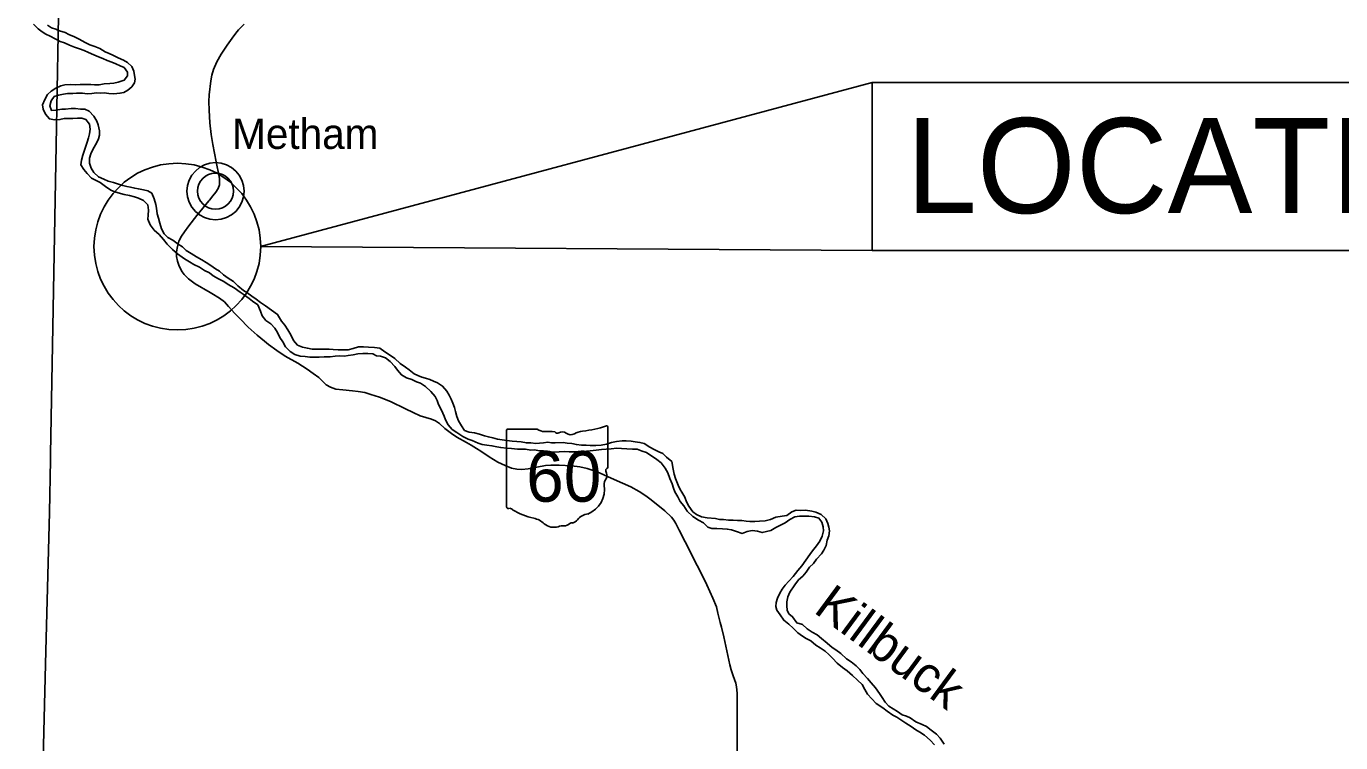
# Model space of a CAD drawing. Extents: x -6.3 to 34, y 0 to 22.
# Drawn here: x 1.879 to 4.228, y 15.677 to 16.958 of the extents above; entities that cross this region are included whole.
import ezdxf

# ---------------------------------------------------------------- set-up
doc = ezdxf.new("R2010")
doc.units = 0
for name, color, linetype in [('BR_P_Gen_Text', 7, 'Continuous'), ('Default', 7, 'Continuous'), ('GM_X_Major_River', 7, 'Continuous'), ('GM_X_Major_River_Text', 7, 'Continuous'), ('GM_X_State_Location', 7, 'Continuous'), ('GM_X_State_Route', 7, 'Continuous'), ('GM_X_State_Shield', 7, 'Continuous'), ('GM_X_Township', 7, 'Continuous'), ('GM_X_Unincorporated', 7, 'Continuous'), ('GM_X_Unincorporated_Location', 7, 'Continuous'), ('GM_X_Unincorporated_Text', 7, 'Continuous')]:
    doc.layers.add(name, color=color, linetype=linetype)

msp = doc.modelspace()

# ---------------------------------------------------------------- linework, layer by layer
at = {"layer": 'BR_P_Gen_Text'}
for points in [[(3.3908, 16.857), (3.3908, 16.5568), (2.2979, 16.5637)], [(3.3908, 16.857), (4.7995, 16.857), (4.7995, 16.5568), (3.3908, 16.5568)]]:
    msp.add_lwpolyline(points, close=True, dxfattribs=at)
at = {"layer": 'Default'}
msp.add_circle((2.149, 16.5637), 0.149, dxfattribs=at)
at = {"layer": 'GM_X_Major_River'}
for points in [[(1.8916, 16.9615), (1.9004, 16.9532), (1.9074, 16.9475), (1.9141, 16.9436), (1.9219, 16.94), (1.9307, 16.9353), (1.9398, 16.9307), (1.9471, 16.9278), (1.9562, 16.9237), (1.9652, 16.9203), (1.9743, 16.9175), (1.9823, 16.9144), (1.9904, 16.9108), (1.9997, 16.9066), (2.0078, 16.903), (2.0158, 16.9002), (2.0238, 16.8963), (2.0319, 16.8937), (2.0389, 16.8903), (2.0469, 16.8867), (2.0539, 16.8841), (2.0599, 16.8756), (2.0599, 16.8691), (2.054, 16.8615), (2.0434, 16.8576), (2.0353, 16.8558), (2.0286, 16.8552), (2.018, 16.8545), (2.0094, 16.8531), (2.0011, 16.8529), (1.9944, 16.8534), (1.9752, 16.8533), (1.9669, 16.8528), (1.9581, 16.8536), (1.948, 16.853), (1.941, 16.8512), (1.932, 16.847), (1.9237, 16.8418), (1.917, 16.8358), (1.912, 16.827), (1.9079, 16.8171), (1.9092, 16.8093), (1.9134, 16.8005), (1.9202, 16.7919), (1.9295, 16.7904), (1.9391, 16.7909), (1.9468, 16.7925), (1.9541, 16.7928), (1.9624, 16.7925), (1.9707, 16.7931), (1.9785, 16.7931), (1.9855, 16.791), (1.9922, 16.7827), (1.9933, 16.7736), (1.9917, 16.7653), (1.9902, 16.7583), (1.9876, 16.7502), (1.9856, 16.7432), (1.9825, 16.7341), (1.9799, 16.7271), (1.9778, 16.718), (1.9766, 16.7097), (1.982, 16.7014), (1.9875, 16.6946), (1.9953, 16.6861), (2.0028, 16.6822), (2.0113, 16.6781), (2.0204, 16.6713), (2.03, 16.6649), (2.037, 16.6618), (2.0471, 16.6589), (2.0541, 16.6571), (2.0637, 16.6548), (2.0723, 16.6525), (2.0798, 16.6501), (2.0886, 16.646), (2.0962, 16.6382), (2.0975, 16.6291), (2.0967, 16.62), (2.0965, 16.613), (2.1004, 16.6029), (2.1074, 16.5933), (2.1165, 16.5853), (2.1243, 16.5765), (2.1308, 16.5679), (2.1406, 16.5583), (2.1492, 16.5508), (2.1615, 16.5418), (2.1706, 16.5366), (2.1787, 16.5317), (2.1885, 16.5271), (2.1976, 16.5209), (2.2062, 16.5168), (2.213, 16.5116), (2.2226, 16.5062), (2.232, 16.5012)], [(2.2003, 16.5353), (2.1925, 16.54), (2.1832, 16.5454), (2.1736, 16.5511), (2.1645, 16.5565), (2.158, 16.563), (2.1507, 16.5682), (2.1411, 16.5752), (2.132, 16.5801), (2.1253, 16.5866), (2.1206, 16.5954), (2.1177, 16.6058), (2.1151, 16.6146), (2.113, 16.6224), (2.1117, 16.6323), (2.1104, 16.639), (2.1078, 16.6492), (2.1031, 16.659), (2.0964, 16.6634), (2.0883, 16.6652), (2.0795, 16.6668), (2.0728, 16.6681), (2.0655, 16.6699), (2.0585, 16.6714), (2.0515, 16.6727), (2.044, 16.6755), (2.0347, 16.6784), (2.0253, 16.6809), (2.0176, 16.6843), (2.0082, 16.6887), (1.9996, 16.6962), (1.995, 16.7037), (1.9921, 16.7128), (1.9921, 16.7219), (1.9944, 16.7297), (1.9988, 16.7386), (2.0047, 16.7487), (2.0081, 16.7562), (2.0096, 16.763), (2.0101, 16.7708), (2.0072, 16.7812), (2.0049, 16.7879), (2, 16.797), (1.9914, 16.8056), (1.9836, 16.8092), (1.9761, 16.8097), (1.967, 16.8107), (1.959, 16.8104), (1.9491, 16.8096), (1.9424, 16.8094), (1.932, 16.8078), (1.924, 16.8073), (1.9209, 16.8156), (1.9232, 16.8241), (1.9291, 16.8319), (1.9366, 16.8345), (1.9457, 16.8364), (1.9527, 16.8374), (1.9623, 16.8377), (1.969, 16.8383), (1.9794, 16.838), (1.988, 16.837), (1.996, 16.8373), (2.0045, 16.8388), (2.0113, 16.8383), (2.0183, 16.8389), (2.0266, 16.8376), (2.0356, 16.8371), (2.0463, 16.8379), (2.0535, 16.8392), (2.0602, 16.8431), (2.0677, 16.8496), (2.0724, 16.8566), (2.0737, 16.8631), (2.0726, 16.8699), (2.071, 16.8772), (2.0679, 16.8857), (2.0601, 16.893), (2.0526, 16.8971), (2.043, 16.9013), (2.0339, 16.9059), (2.0272, 16.9088), (2.0199, 16.9121), (2.0103, 16.9176), (2.0015, 16.9214), (1.9927, 16.9245), (1.9844, 16.9287), (1.9735, 16.9346), (1.9649, 16.939), (1.9551, 16.9432), (1.9483, 16.9465), (1.9385, 16.9494), (1.9315, 16.9522), (1.9242, 16.9551), (1.9167, 16.9595)], [(3.0014, 16.2007), (2.9936, 16.2049), (2.9833, 16.2114), (2.9758, 16.2137), (2.9675, 16.2147), (2.9599, 16.216), (2.9511, 16.2162), (2.9439, 16.2162), (2.9338, 16.2152), (2.9252, 16.2136), (2.9162, 16.2107), (2.9068, 16.2089), (2.8967, 16.2081), (2.8871, 16.2083), (2.8796, 16.2086), (2.8716, 16.2088), (2.8623, 16.2098), (2.854, 16.2114), (2.8459, 16.2124), (2.8384, 16.2132), (2.8244, 16.2129), (2.8177, 16.2131), (2.8109, 16.2139), (2.8032, 16.2126), (2.7964, 16.212), (2.7897, 16.2118), (2.7809, 16.2128), (2.7729, 16.2128), (2.7633, 16.2146), (2.756, 16.2151), (2.7475, 16.2158), (2.7381, 16.2171), (2.7293, 16.2181), (2.721, 16.2192), (2.713, 16.2215), (2.7049, 16.2233), (2.6977, 16.2256), (2.6891, 16.2282), (2.6801, 16.2305), (2.6707, 16.2321), (2.6624, 16.2352), (2.6567, 16.2432), (2.6515, 16.252), (2.6484, 16.2601), (2.646, 16.2689), (2.6442, 16.2759), (2.6413, 16.284), (2.6385, 16.2912), (2.6348, 16.2982), (2.6304, 16.3055), (2.6231, 16.3143), (2.6138, 16.32), (2.607, 16.3231), (2.6, 16.326), (2.5925, 16.3283), (2.5858, 16.3301), (2.579, 16.3334), (2.572, 16.3365), (2.5635, 16.3433), (2.5567, 16.3479), (2.5471, 16.3549), (2.5378, 16.3635), (2.5279, 16.37), (2.5199, 16.3754), (2.511, 16.3821), (2.5015, 16.3834), (2.4908, 16.3839), (2.482, 16.3847), (2.4727, 16.3847), (2.4634, 16.3818), (2.4543, 16.3794), (2.4452, 16.3792), (2.4362, 16.3791), (2.4274, 16.3796), (2.4201, 16.3804), (2.4115, 16.3804), (2.4004, 16.3801), (2.39, 16.3801), (2.3815, 16.3819), (2.3727, 16.384), (2.3638, 16.3876), (2.3566, 16.3961), (2.3519, 16.4057), (2.3462, 16.4146), (2.341, 16.4231), (2.335, 16.4301), (2.328, 16.4426), (2.3064, 16.4577), (2.2979, 16.4637), (2.2898, 16.4696), (2.282, 16.4753), (2.2734, 16.4815), (2.2672, 16.4854), (2.2571, 16.4936), (2.2496, 16.5016), (2.2397, 16.5071), (2.2312, 16.513), (2.2242, 16.5195), (2.2169, 16.5242), (2.2089, 16.5301), (2.2003, 16.5353)], [(2.2319, 16.5013), (2.24, 16.4959), (2.2506, 16.4897), (2.2613, 16.4822), (2.2665, 16.4789), (2.2776, 16.4709), (2.2831, 16.4659), (2.2927, 16.4598), (2.2974, 16.4485), (2.3008, 16.4402), (2.3073, 16.4314), (2.3163, 16.4254), (2.3234, 16.4181), (2.3278, 16.4101), (2.3322, 16.4013), (2.3377, 16.3935), (2.3423, 16.3842), (2.3509, 16.3759), (2.359, 16.3709), (2.3683, 16.3681), (2.3776, 16.3671), (2.3859, 16.3661), (2.3932, 16.3658), (2.4022, 16.3661), (2.4116, 16.3664), (2.4219, 16.3669), (2.431, 16.368), (2.4388, 16.3682), (2.4476, 16.368), (2.4543, 16.369), (2.4631, 16.3704), (2.4717, 16.3719), (2.4805, 16.3727), (2.4896, 16.3727), (2.4981, 16.3722), (2.5051, 16.3686), (2.5121, 16.3681), (2.5212, 16.3648), (2.5295, 16.358), (2.5375, 16.3495), (2.5422, 16.3427), (2.5495, 16.3342), (2.5586, 16.329), (2.5679, 16.3259), (2.5762, 16.322), (2.5835, 16.3194), (2.5926, 16.3137), (2.6022, 16.3049), (2.6097, 16.2958), (2.6133, 16.2888), (2.6157, 16.2816), (2.6211, 16.2712), (2.6256, 16.2608), (2.6282, 16.2538), (2.6331, 16.245), (2.6399, 16.2369), (2.6487, 16.2312), (2.6591, 16.2242), (2.6687, 16.2196), (2.6762, 16.2173), (2.6866, 16.2123), (2.6938, 16.2098), (2.7021, 16.2087), (2.7112, 16.2075), (2.7203, 16.2057), (2.727, 16.2044), (2.7371, 16.2036), (2.7462, 16.2026), (2.7568, 16.2016), (2.7638, 16.2016), (2.7711, 16.2013), (2.7807, 16.1998), (2.7879, 16.2001), (2.7954, 16.1988), (2.8037, 16.1985), (2.8112, 16.1973), (2.8195, 16.1962), (2.8312, 16.1965), (2.841, 16.1971), (2.8491, 16.1966), (2.8587, 16.1968), (2.8654, 16.1974), (2.8732, 16.1974), (2.8866, 16.1984), (2.8973, 16.2), (2.9074, 16.2008), (2.9154, 16.2016), (2.9242, 16.2024), (2.9343, 16.2032), (2.9429, 16.203), (2.9522, 16.202), (2.9623, 16.2017), (2.9711, 16.2015), (2.9797, 16.1978), (2.9877, 16.1958), (3.0059, 16.1828), (3.0139, 16.1769), (3.0207, 16.1678), (3.0256, 16.1592), (3.029, 16.1491), (3.0334, 16.1398)], [(2.232, 16.5012), (2.24, 16.4959), (2.2506, 16.4897), (2.2613, 16.4822), (2.2665, 16.4789), (2.2776, 16.4709), (2.2831, 16.4659), (2.2927, 16.4598), (2.2974, 16.4485), (2.3008, 16.4402), (2.3073, 16.4314), (2.3163, 16.4254), (2.3234, 16.4181), (2.3278, 16.4101), (2.3322, 16.4013), (2.3377, 16.3935), (2.3423, 16.3842), (2.3509, 16.3759), (2.359, 16.3709), (2.3683, 16.3681), (2.3776, 16.3671), (2.3859, 16.3661), (2.3932, 16.3658), (2.4022, 16.3661), (2.4116, 16.3664), (2.4219, 16.3669), (2.431, 16.368), (2.4388, 16.3682), (2.4476, 16.368), (2.4543, 16.369), (2.4631, 16.3704), (2.4717, 16.3719), (2.4805, 16.3727), (2.4896, 16.3727), (2.4981, 16.3722), (2.5051, 16.3686), (2.5121, 16.3681), (2.5212, 16.3648), (2.5295, 16.358), (2.5375, 16.3495), (2.5422, 16.3427), (2.5495, 16.3342), (2.5586, 16.329), (2.5679, 16.3259), (2.5762, 16.322), (2.5835, 16.3194), (2.5926, 16.3137), (2.6022, 16.3049), (2.6097, 16.2958), (2.6133, 16.2888), (2.6157, 16.2816), (2.6211, 16.2712), (2.6256, 16.2608), (2.6282, 16.2538), (2.6331, 16.245), (2.6399, 16.2369), (2.6487, 16.2312), (2.6591, 16.2242), (2.6687, 16.2196), (2.6762, 16.2173), (2.6866, 16.2123), (2.6938, 16.2098), (2.7021, 16.2087), (2.7112, 16.2075), (2.7203, 16.2057), (2.727, 16.2044), (2.7371, 16.2036), (2.7462, 16.2026), (2.7568, 16.2016), (2.7638, 16.2016), (2.7711, 16.2013), (2.7807, 16.1998), (2.7879, 16.2001), (2.7954, 16.1988), (2.8037, 16.1985), (2.8112, 16.1973), (2.8195, 16.1962), (2.8312, 16.1965), (2.841, 16.1971), (2.8491, 16.1966), (2.8587, 16.1968), (2.8654, 16.1974), (2.8732, 16.1974), (2.8866, 16.1984), (2.8973, 16.2), (2.9074, 16.2008), (2.9154, 16.2016), (2.9242, 16.2024), (2.9343, 16.2032), (2.9429, 16.203), (2.9522, 16.202), (2.9623, 16.2017), (2.9711, 16.2015), (2.9797, 16.1978), (2.9877, 16.1958), (3.0059, 16.1828), (3.0139, 16.1769), (3.0207, 16.1678), (3.0256, 16.1592), (3.029, 16.1491), (3.0334, 16.1398)], [(3.5197, 15.6741), (3.5122, 15.6848), (3.5059, 15.6918), (3.4966, 15.699), (3.4878, 15.7058), (3.4803, 15.7091), (3.4688, 15.7138), (3.459, 15.7211), (3.4522, 15.7239), (3.4445, 15.7267), (3.4359, 15.7327), (3.4286, 15.7371), (3.4209, 15.7423), (3.4141, 15.749), (3.4086, 15.7578), (3.4042, 15.7649), (3.3967, 15.7747), (3.3889, 15.7838), (3.3827, 15.7916), (3.3741, 15.8004), (3.3686, 15.8076), (3.3621, 15.8139), (3.3531, 15.8216), (3.345, 15.8266), (3.3346, 15.8362), (3.3261, 15.8429), (3.3193, 15.8468), (3.3105, 15.8548), (3.3006, 15.8631), (3.2926, 15.8693), (3.2835, 15.8745), (3.2747, 15.8802), (3.2664, 15.888), (3.256, 15.8913), (3.2485, 15.902), (3.2417, 15.9072), (3.2391, 15.9139), (3.2381, 15.9212), (3.2386, 15.9287), (3.2401, 15.9373), (3.2437, 15.9461), (3.2525, 15.9591), (3.2595, 15.968), (3.2672, 15.9747), (3.2732, 15.9815), (3.2791, 15.9906), (3.2858, 15.9969), (3.2913, 16.0047), (3.3003, 16.0146), (3.3045, 16.0211), (3.3086, 16.0294), (3.3104, 16.039), (3.3135, 16.0463), (3.3145, 16.0554), (3.3137, 16.0619), (3.3114, 16.0686), (3.3082, 16.0772), (3.2999, 16.0847), (3.2901, 16.0888), (3.2831, 16.0906), (3.2719, 16.0922), (3.2621, 16.0921), (3.2553, 16.0924), (3.2476, 16.0895), (3.2383, 16.083), (3.23, 16.0817), (3.2186, 16.0799), (3.209, 16.0757), (3.1994, 16.0736), (3.1896, 16.0728), (3.181, 16.0725), (3.1722, 16.0722), (3.1655, 16.073), (3.1577, 16.074), (3.1502, 16.074), (3.1424, 16.0743), (3.1344, 16.0748), (3.125, 16.0755), (3.1183, 16.076), (3.111, 16.0773), (3.0962, 16.0789), (3.0856, 16.0805), (3.0771, 16.0846), (3.0706, 16.0895), (3.063, 16.0998), (3.0591, 16.1074), (3.0559, 16.1159), (3.0507, 16.1247), (3.0478, 16.1294), (3.0442, 16.1374), (3.0392, 16.1491), (3.0368, 16.1571), (3.035, 16.166), (3.0328, 16.1792), (3.0235, 16.187), (3.0167, 16.1938), (3.0095, 16.1969), (3.0014, 16.2007)], [(3.0334, 16.1398), (3.036, 16.132), (3.0381, 16.1252), (3.0438, 16.1161), (3.048, 16.1078), (3.054, 16.1001), (3.0602, 16.0905), (3.0701, 16.0814), (3.0807, 16.0744), (3.0893, 16.0697), (3.0971, 16.0622), (3.1041, 16.0594), (3.1134, 16.0599), (3.1233, 16.0589), (3.1318, 16.0587), (3.1393, 16.0571), (3.1484, 16.0543), (3.1585, 16.0509), (3.1676, 16.0546), (3.1766, 16.0561), (3.1857, 16.0551), (3.1943, 16.0525), (3.2018, 16.0541), (3.2095, 16.0562), (3.2186, 16.0614), (3.2259, 16.0651), (3.2354, 16.07), (3.244, 16.0757), (3.2528, 16.0804), (3.2611, 16.0815), (3.2678, 16.082), (3.2779, 16.082), (3.2878, 16.0805), (3.2958, 16.0784), (3.3012, 16.0712), (3.3033, 16.0624), (3.3039, 16.0553), (3.3018, 16.0462), (3.2974, 16.0369), (3.2915, 16.0288), (3.2842, 16.0195), (3.2793, 16.013), (3.2726, 16.0028), (3.2649, 15.9927), (3.2579, 15.9849), (3.2499, 15.9737), (3.2419, 15.9656), (3.2354, 15.9583), (3.2302, 15.9513), (3.2261, 15.944), (3.2215, 15.9354), (3.2191, 15.9271), (3.2186, 15.9204), (3.2202, 15.9139), (3.2262, 15.9056), (3.2329, 15.8957), (3.2418, 15.8887), (3.2496, 15.8815), (3.2581, 15.8729), (3.2664, 15.8669), (3.2732, 15.8628), (3.2812, 15.8587), (3.2903, 15.8511), (3.2981, 15.8462), (3.3069, 15.8405), (3.3134, 15.8346), (3.3201, 15.8281), (3.3282, 15.819), (3.3378, 15.811), (3.3464, 15.805), (3.356, 15.797), (3.3645, 15.7884), (3.3728, 15.7806), (3.378, 15.7721), (3.3827, 15.7635), (3.39, 15.755), (3.3983, 15.7469), (3.4097, 15.7391), (3.418, 15.7334), (3.4276, 15.7262), (3.4349, 15.7226), (3.4422, 15.7179), (3.4512, 15.7117), (3.4606, 15.7057), (3.4689, 15.6995), (3.4759, 15.6954), (3.4847, 15.6904), (3.4948, 15.6814), (3.5026, 15.6731)]]:
    msp.add_lwpolyline(points, dxfattribs=at)
at = {"layer": 'GM_X_State_Route'}
msp.add_line((2.2053, 16.6457), (2.2062, 16.6468), dxfattribs=at)
for points in [[(2.2244, 16.6743), (2.2244, 16.6791), (2.2242, 16.6849), (2.2237, 16.6893), (2.2186, 16.7155), (2.2124, 16.7462), (2.2095, 16.764), (2.207, 16.7848), (2.2056, 16.8078), (2.2052, 16.8229), (2.2061, 16.8352), (2.2091, 16.8602), (2.2107, 16.8702), (2.2137, 16.8806), (2.2193, 16.894), (2.2274, 16.908), (2.2383, 16.924), (2.2467, 16.9362), (2.2538, 16.9455), (2.2585, 16.9515), (2.2634, 16.9566), (2.2685, 16.9611)], [(2.2062, 16.6468), (2.2123, 16.6543), (2.2175, 16.6613), (2.2218, 16.6678), (2.2244, 16.6743)], [(2.2106, 16.4797), (2.2077, 16.4814), (2.1808, 16.4972), (2.169, 16.5062), (2.1611, 16.5141), (2.1574, 16.5185), (2.1551, 16.5227), (2.1514, 16.5303), (2.1491, 16.5375), (2.1476, 16.5459), (2.1476, 16.5544), (2.149, 16.5637), (2.1519, 16.5735), (2.1567, 16.5823), (2.1618, 16.5903), (2.1694, 16.601), (2.1836, 16.6191), (2.2053, 16.6457)], [(3.1494, 15.6519), (3.1498, 15.7411), (3.1495, 15.7651), (3.1485, 15.7764), (3.1472, 15.7831), (3.1426, 15.7965), (3.139, 15.8072), (3.1365, 15.8161), (3.1256, 15.8662), (3.1215, 15.8832), (3.1194, 15.8919), (3.1153, 15.9085), (3.1124, 15.9196), (3.1062, 15.9349), (3.0952, 15.9589), (3.0799, 15.9903), (3.0766, 15.9965), (3.0672, 16.0149), (3.0461, 16.0567), (3.04, 16.0687), (3.0364, 16.0746), (3.0321, 16.0802), (3.0204, 16.091), (2.9956, 16.1111), (2.9865, 16.1182), (2.9747, 16.126), (2.9596, 16.134), (2.93, 16.1475), (2.8991, 16.161), (2.8817, 16.1668), (2.8683, 16.1697), (2.8536, 16.1718), (2.8315, 16.1729), (2.8164, 16.1729), (2.8073, 16.1721), (2.7763, 16.1665), (2.7647, 16.1652), (2.7559, 16.1656), (2.7465, 16.1678), (2.7352, 16.1721), (2.7221, 16.1784), (2.7066, 16.1879), (2.6913, 16.1981), (2.6834, 16.203), (2.6741, 16.2085), (2.6658, 16.2134), (2.6487, 16.223), (2.6388, 16.2296), (2.6272, 16.2385), (2.6173, 16.2474), (2.6103, 16.2523), (2.6034, 16.2553), (2.5933, 16.2582), (2.5832, 16.2614), (2.5705, 16.2673), (2.5567, 16.2739), (2.5298, 16.2865), (2.5105, 16.2944), (2.495, 16.2994), (2.4838, 16.303), (2.472, 16.3048), (2.462, 16.3056), (2.4448, 16.3074), (2.4325, 16.3091), (2.423, 16.3123), (2.415, 16.3168), (2.4095, 16.3217), (2.4016, 16.3294), (2.392, 16.337), (2.3812, 16.3447), (2.3641, 16.3551), (2.3418, 16.3679), (2.3269, 16.3777), (2.312, 16.3889), (2.3048, 16.3945), (2.2919, 16.4052), (2.2758, 16.4198), (2.2612, 16.4344), (2.2517, 16.4441), (2.2406, 16.4569), (2.2332, 16.4649), (2.2244, 16.4714), (2.2106, 16.4797)]]:
    msp.add_lwpolyline(points, dxfattribs=at)
at = {"layer": 'GM_X_State_Shield'}
for p, q in [((2.7376, 16.2351), (2.7376, 16.0979)), ((2.7923, 16.2374), (2.7393, 16.2374)), ((2.9183, 16.1691), (2.9183, 16.2408)), ((2.9182, 16.1691), (2.9183, 16.1691))]:
    msp.add_line(p, q, dxfattribs=at)
for centre, radius, start, end in [((2.7396, 16.2354), 0.00209, 98.1301, 188.1301), ((2.8049, 16.2534), 0.0203, 231.6195, 271.1119), ((2.8539, 16.4244), 0.1916, 275.8445, 288.9065), ((2.9163, 16.2411), 0.00201, 351.8621, 97.738), ((2.8116, 16.1604), 0.0729, 80.4867, 94.9883), ((2.8281, 16.2361), 0.00586, 219.7921, 297.1024), ((2.8367, 16.2202), 0.0122, 54.4667, 119.1411), ((2.8525, 16.242), 0.0147, 233.8562, 294.8282), ((2.8783, 16.1956), 0.0386, 97.3462, 120.7689), ((2.9178, 16.1638), 0.00311, 107.944, 210.337), ((2.9161, 16.1688), 0.00215, 289.6038, 7.7341), ((2.9255, 16.1391), 0.0136, 136.8065, 186.9296), ((2.898, 16.1548), 0.0187, 340.033, 23.6496), ((2.8646, 16.1299), 0.0479, 292.3089, 8.9858), ((2.7397, 16.0976), 0.00211, 171.9584, 258.3066), ((2.74, 16.1117), 0.0161, 267.339, 280.6039), ((2.7433, 16.09), 0.00581, 29.7484, 93.2717), ((2.8166, 16.2132), 0.1384, 240.4129, 257.1985), ((2.7754, 16.0363), 0.0433, 47.1842, 75.836), ((2.8533, 16.0658), 0.00412, 65.7517, 132.6484), ((2.8516, 16.0846), 0.0155, 282.8732, 323.2771), ((2.8848, 16.0594), 0.0263, 94.4031, 142.5768), ((2.8222, 16.0893), 0.0275, 230.7004, 286.2918), ((2.8381, 16.0419), 0.0226, 85.6951, 111.2099), ((2.8401, 16.0791), 0.0146, 268.777, 315.5493)]:
    msp.add_arc(centre, radius, start, end, dxfattribs=at)
at = {"layer": 'GM_X_Township'}
msp.add_lwpolyline([(1.879, 14.2362), (1.8808, 14.3961), (1.8946, 15.0244), (1.9035, 15.4307), (1.9141, 15.8408), (1.9205, 16.0883), (1.9222, 16.1824), (1.9224, 16.1926), (1.9324, 16.7453), (1.9397, 17.1416)], dxfattribs=at)
at = {"layer": 'GM_X_Unincorporated'}
for radius in [0.051, 0.0323]:
    msp.add_circle((2.2172, 16.6628), radius, dxfattribs=at)
at = {"layer": 'GM_X_Unincorporated_Location'}
msp.add_line((2.2172, 16.6628), (2.2172, 16.6628), dxfattribs=at)

# ---------------------------------------------------------------- texts
at = {"layer": 'BR_P_Gen_Text'}
msp.add_text('LOCATION 1', height=0.17, dxfattribs=at).set_placement((3.4516, 16.6236))
at = {"layer": 'GM_X_Major_River_Text'}
msp.add_text('Killbuck', height=0.0649, rotation=323.6046, dxfattribs=at).set_placement((3.2842, 15.911))
at = {"layer": 'GM_X_State_Location'}
msp.add_text('60', height=0.00013, rotation=0, dxfattribs=at).set_placement((2.7932, 16.1479))
for s in ['s', 'r']:
    msp.add_text(s, height=0.00013, dxfattribs=at).set_placement((2.8259, 16.1574))
at = {"layer": 'GM_X_State_Shield'}
msp.add_text('60', height=0.09035, dxfattribs=at).set_placement((2.7725, 16.1076))
at = {"layer": 'GM_X_Unincorporated_Text'}
msp.add_text('Metham', height=0.05413, rotation=0, dxfattribs=at).set_placement((2.2469, 16.7383))

doc.saveas('drawing.dxf')
